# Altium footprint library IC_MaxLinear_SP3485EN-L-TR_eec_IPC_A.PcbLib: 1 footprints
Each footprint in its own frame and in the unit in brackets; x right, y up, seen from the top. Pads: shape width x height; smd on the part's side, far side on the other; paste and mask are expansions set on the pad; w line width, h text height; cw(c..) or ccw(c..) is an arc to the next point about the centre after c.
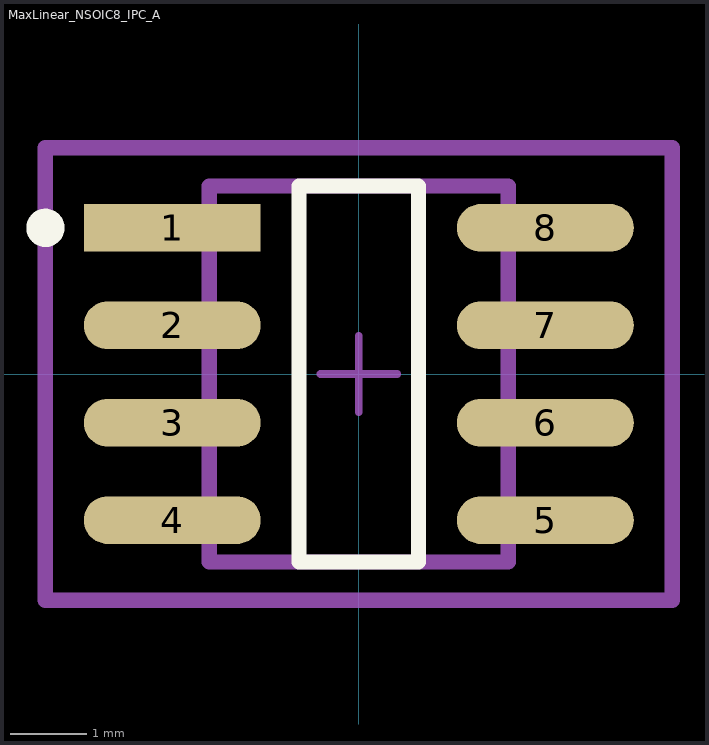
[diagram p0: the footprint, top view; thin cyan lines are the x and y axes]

## MaxLinear_NSOIC8_IPC_A [mil]
pads (8):
  rect 90.8x24.49 smd paste+0 mask+0: 1(-95.75,75)
  rrect100% 90.8x24.49 smd paste+0 mask+0: 2(-95.75,25) 3(-95.75,-25) 4(-95.75,-75) 5(95.75,-75) 6(95.75,-25) 7(95.75,25) 8(95.75,75)
Top Overlay:
  circle w9.84: c-160.84,75 r4.92
  lines w7.87: -30.67,-96.46 30.67,-96.46 30.67,96.46 -30.67,96.46 -30.67,-96.46
Mechanical 10:
  lines w7.87: -160.84,-116.14 160.84,-116.14 160.84,116.14 -160.84,116.14 -160.84,-116.14
  text ".Designator" at 0,7.41 h39.37
Mechanical 12:
  lines w7.87: -76.77,-96.46 76.77,-96.46 76.77,96.46 -76.77,96.46 -76.77,-96.46
Mechanical 15:
  lines w3.94: -19.68,0 19.68,0 ; 0,-19.68 0,19.68
  lines w7.87: -160.84,-116.14 160.84,-116.14 160.84,116.14 -160.84,116.14 -160.84,-116.14
3D body "IC_MaxLinear_SP3485EN-L-TR_eec.STEP": height 10, standoff 0, extent -160.84,-116.14 160.84,116.14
